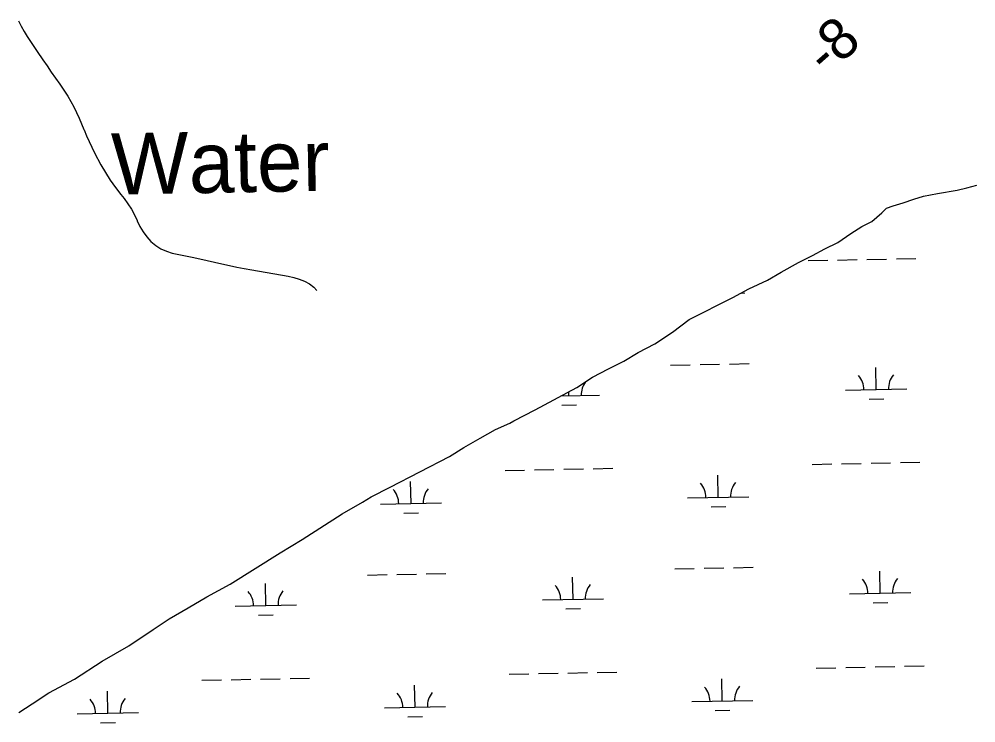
# Model space of a CAD drawing. Extents: x 3989314 to 4027622, y 243956 to 270014.
# Drawn here: x 4015842 to 4017404, y 263759 to 264908 of the extents above; entities that cross this region are included whole.
import ezdxf

# ---------------------------------------------------------------- set-up
doc = ezdxf.new("R2010")
doc.units = 0
for name, color, linetype in [('V-RIVR-EDGE', 7, 'Continuous'), ('V-RIVR-IDEN', 7, 'Continuous'), ('V-RIVR-RANG', 7, 'Continuous'), ('V-TOPO-MINR', 7, 'Continuous'), ('V-WETL-SWMP', 7, 'Continuous')]:
    doc.layers.add(name, color=color, linetype=linetype)

msp = doc.modelspace()

# ---------------------------------------------------------------- linework, layer by layer
at = {"layer": 'V-RIVR-EDGE'}
msp.add_lwpolyline([(4015841.4, 263775.6), (4015862.9, 263789.9), (4015890.4, 263807.8), (4015932.3, 263830.4), (4015977.5, 263859.5), (4016020.9, 263884.8), (4016060.7, 263911.4), (4016086.9, 263928.5), (4016117.9, 263946.9), (4016148.3, 263964.8), (4016186.3, 263985.3), (4016267.9, 264036.6), (4016303.8, 264058.5), (4016369.5, 264100.4), (4016402.5, 264119.4), (4016416.7, 264127.8), (4016447.9, 264143.5), (4016544.8, 264193.8), (4016567.8, 264208.5), (4016594.4, 264224), (4016619.9, 264237.8), (4016643, 264248), (4016649.7, 264251.8), (4016684.6, 264270.1), (4016752.6, 264306.7), (4016778.3, 264323.1), (4016804.4, 264337.2), (4016829.2, 264349.2), (4016852.9, 264363.7), (4016879.7, 264377.7), (4016908.7, 264396.9), (4016936.1, 264417.6), (4017007.5, 264453.3), (4017033.4, 264467.3), (4017063.7, 264481.9), (4017086.1, 264494.6), (4017114.8, 264510.3), (4017137.2, 264521.8), (4017157.5, 264533.1), (4017179, 264543.1), (4017199.9, 264557.7), (4017218, 264569.2), (4017234.6, 264577.6), (4017250.7, 264591.8), (4017258.5, 264599.5), (4017269.3, 264603.2), (4017285.6, 264608), (4017302.8, 264614.2), (4017318.8, 264619), (4017341.7, 264623.3), (4017373.7, 264628.6), (4017389.7, 264632.6), (4017405.8, 264637)], dxfattribs=at)
at = {"layer": 'V-TOPO-MINR'}
msp.add_lwpolyline([(4015840.7, 264905.4), (4015845.2, 264896.7), (4015849.9, 264888), (4015854.9, 264879.6), (4015860.1, 264871.2), (4015865.5, 264863), (4015871, 264854.9), (4015880.6, 264841.2), (4015887.4, 264831.4), (4015894.2, 264821.5), (4015901.1, 264811.7), (4015907.9, 264801.9), (4015910.1, 264798.7), (4015915.7, 264790.4), (4015921.1, 264781.9), (4015926.1, 264773.3), (4015930.9, 264764.5), (4015935.4, 264755.5), (4015939.7, 264746.4), (4015943.7, 264737.2), (4015947.4, 264727.9), (4015947.7, 264727.2), (4015951.6, 264717.6), (4015955.8, 264708), (4015960.3, 264698.7), (4015965, 264689.4), (4015975.3, 264670.2), (4015982.6, 264657.5), (4015990.4, 264645), (4015998.8, 264633), (4016007.7, 264621.4), (4016013, 264614.8), (4016019.2, 264606.4), (4016025, 264597.7), (4016029.9, 264588.5), (4016034.4, 264579.1), (4016034.5, 264578.7), (4016039, 264569.6), (4016044.1, 264560.8), (4016050.3, 264552.7), (4016057, 264545), (4016064.7, 264538.5), (4016073, 264532.9), (4016082.1, 264529), (4016091.7, 264526), (4016124.4, 264519.1), (4016136.6, 264516.5), (4016148.7, 264513.8), (4016160.8, 264511.1), (4016172.9, 264508.3), (4016185, 264505.7), (4016197.2, 264503.1), (4016209.3, 264500.8), (4016221.6, 264498.6), (4016281.1, 264488.4), (4016290.2, 264486.3), (4016299.1, 264483.6), (4016307.6, 264480), (4016315.8, 264475.7), (4016323, 264470.2), (4016328.1, 264465.1)], dxfattribs=at)
at = {"layer": 'V-WETL-SWMP'}
for p, q in [((4017130.4, 264513.6), (4017162.4, 264514.2)), ((4017178.4, 264514.6), (4017210.4, 264515.2)), ((4017226.4, 264515.5), (4017258.4, 264516.2)), ((4017274.4, 264516.5), (4017306.4, 264517.1)), ((4017021.2, 264460.7), (4017026.9, 264460.8)), ((4016905.8, 264342.9), (4016937.8, 264343.6)), ((4016953.8, 264343.9), (4016985.8, 264344.5)), ((4017001.8, 264344.8), (4017033.8, 264345.5)), ((4017241.5, 264303.2), (4017240.8, 264339.2)), ((4016726.9, 264292.9), (4016789.7, 264294.2)), ((4016739.7, 264293.2), (4016739.6, 264299.7)), ((4017191.5, 264302.2), (4017291.5, 264304.2)), ((4016728, 264277.5), (4016752, 264278)), ((4017229.8, 264287.5), (4017253.8, 264288)), ((4017233.1, 264182.9), (4017265, 264183.5)), ((4017281, 264183.9), (4017313, 264184.5)), ((4016635.3, 264171), (4016667.3, 264171.6)), ((4016683.3, 264171.9), (4016715.2, 264172.6)), ((4016731.2, 264172.9), (4016763.2, 264173.5)), ((4016779.2, 264173.9), (4016811.2, 264174.5)), ((4017137.1, 264181), (4017169.1, 264181.6)), ((4017185.1, 264182), (4017217.1, 264182.6)), ((4016481.7, 264117.2), (4016481, 264153.2)), ((4016983.5, 264127.2), (4016982.8, 264163.2)), ((4016933.5, 264126.2), (4017033.5, 264128.2)), ((4016431.7, 264116.2), (4016531.7, 264118.2)), ((4016971.8, 264111.5), (4016995.8, 264112)), ((4016470, 264101.5), (4016494, 264102)), ((4016960.4, 264011.3), (4016992.4, 264011.9)), ((4017008.4, 264012.2), (4017040.4, 264012.9)), ((4016410.6, 264000.3), (4016442.6, 264000.9)), ((4016458.6, 264001.3), (4016490.6, 264001.9)), ((4016506.6, 264002.2), (4016538.6, 264002.9)), ((4016746.3, 263960.6), (4016745.6, 263996.6)), ((4016912.4, 264010.3), (4016944.4, 264010.9)), ((4017248.1, 263970.6), (4017247.4, 264006.6)), ((4016244.5, 263950.6), (4016243.8, 263986.6)), ((4017198.1, 263969.6), (4017298.1, 263971.6)), ((4016194.5, 263949.6), (4016294.5, 263951.6)), ((4016696.3, 263959.6), (4016796.3, 263961.6)), ((4017236.4, 263954.9), (4017260.4, 263955.4)), ((4016232.8, 263934.9), (4016256.8, 263935.4)), ((4016734.6, 263944.9), (4016758.6, 263945.4)), ((4016689.9, 263839.3), (4016721.9, 263840)), ((4016737.9, 263840.3), (4016769.9, 263840.9)), ((4016785.9, 263841.3), (4016817.9, 263841.9)), ((4017143.7, 263848.4), (4017175.7, 263849)), ((4017191.7, 263849.3), (4017223.7, 263850)), ((4017239.7, 263850.3), (4017271.7, 263850.9)), ((4017287.7, 263851.3), (4017319.7, 263851.9)), ((4016140.1, 263828.4), (4016172.1, 263829)), ((4016188.1, 263829.3), (4016220.1, 263830)), ((4016236.1, 263830.3), (4016268.1, 263830.9)), ((4016284.1, 263831.3), (4016316, 263831.9)), ((4016641.9, 263838.4), (4016673.9, 263839)), ((4016990.1, 263794.6), (4016989.4, 263830.6)), ((4015986.5, 263774.6), (4015985.8, 263810.6)), ((4016488.3, 263784.6), (4016487.6, 263820.6)), ((4016940.2, 263793.6), (4017040.1, 263795.6)), ((4016438.3, 263783.6), (4016538.3, 263785.6)), ((4016978.5, 263778.9), (4017002.5, 263779.4)), ((4015936.5, 263773.6), (4016036.5, 263775.6)), ((4016476.6, 263768.9), (4016500.6, 263769.4)), ((4015974.8, 263758.9), (4015998.8, 263759.4))]:
    msp.add_line(p, q, dxfattribs=at)
for points in [[(4017269.3, 264603.2), (4017285.6, 264608), (4017302.8, 264614.2), (4017318.8, 264619), (4017341.7, 264623.3), (4017373.7, 264628.6), (4017389.7, 264632.6), (4017405.8, 264637)], [(4015841.4, 263775.6), (4015862.9, 263789.9), (4015890.4, 263807.8), (4015932.3, 263830.4), (4015977.5, 263859.5), (4016020.9, 263884.8), (4016060.7, 263911.4), (4016086.9, 263928.5), (4016117.9, 263946.9), (4016148.3, 263964.8), (4016186.3, 263985.3), (4016267.9, 264036.6), (4016303.8, 264058.5), (4016369.5, 264100.3), (4016402.5, 264119.4), (4016416.7, 264127.8), (4016447.9, 264143.5), (4016544.8, 264193.8), (4016567.8, 264208.5), (4016594.4, 264224), (4016619.9, 264237.8), (4016643, 264248), (4016649.7, 264251.8), (4016684.6, 264270.1), (4016752.6, 264306.7), (4016778.3, 264323.1), (4016804.4, 264337.2), (4016829.2, 264349.2), (4016852.9, 264363.7), (4016879.7, 264377.7), (4016908.7, 264396.9), (4016936.1, 264417.6), (4017007.5, 264453.3), (4017033.4, 264467.3), (4017063.7, 264481.9), (4017086.1, 264494.6), (4017114.8, 264510.3), (4017137.2, 264521.8), (4017157.5, 264533.1), (4017179, 264543.1), (4017199.9, 264557.7), (4017218, 264569.2), (4017234.6, 264577.6), (4017250.7, 264591.8), (4017258.5, 264599.5), (4017269.3, 264603.2)]]:
    msp.add_lwpolyline(points, dxfattribs=at)
for centre, start, end in [((4017186.3, 264302.5), 0.3699, 41.9135), ((4017296.7, 264304.7), 140.3699, 181.9135), ((4016794.9, 264294.7), 143.6826, 181.9135), ((4016426.5, 264116.6), 0.3699, 41.9135), ((4016536.9, 264118.8), 140.3699, 181.9135), ((4016928.3, 264126.6), 0.3699, 41.9135), ((4017038.7, 264128.8), 140.3699, 181.9135), ((4016691.1, 263959.9), 0.3699, 41.9135), ((4016801.5, 263962.1), 140.3699, 181.9135), ((4017192.9, 263969.9), 0.3699, 41.9135), ((4017303.4, 263972.1), 140.3699, 181.9135), ((4016189.3, 263949.9), 0.3699, 41.9135), ((4016299.7, 263952.1), 140.3699, 181.9135), ((4016543.6, 263786.1), 140.3699, 181.9135), ((4016934.9, 263793.9), 0.3699, 41.9135), ((4017045.4, 263796.1), 140.3699, 181.9135), ((4015931.3, 263773.9), 0.3699, 41.9135), ((4016041.8, 263776.1), 140.3699, 181.9135), ((4016433.1, 263783.9), 0.3699, 41.9135)]:
    msp.add_arc(centre, 35.2, start, end, dxfattribs=at)

# ---------------------------------------------------------------- texts
at = {"layer": 'V-RIVR-IDEN'}
msp.add_text('Water', height=100, rotation=1.0724, dxfattribs=at).set_placement((4015993.1, 264621.2))
at = {"layer": 'V-RIVR-RANG'}
msp.add_text('-8', height=67, rotation=41.2776, dxfattribs=at).set_placement((4017160.2, 264814.8))

doc.saveas('drawing.dxf')
